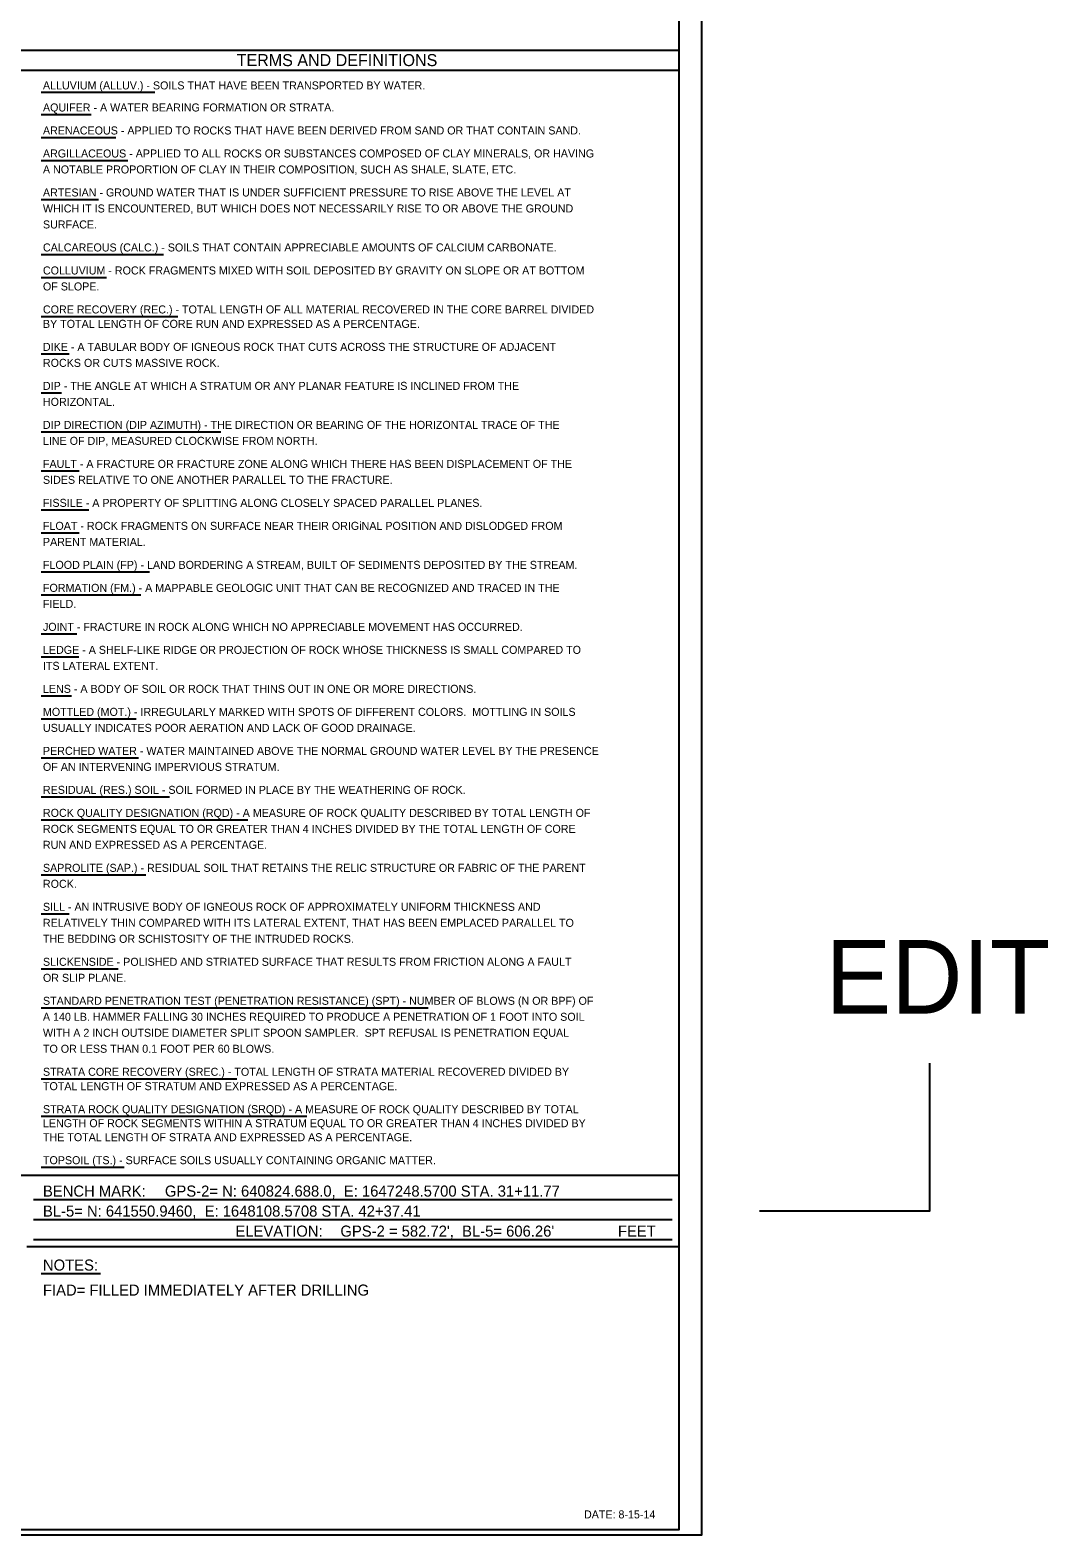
# Model space of a CAD drawing. Extents: x 278618 to 280654, y 171155 to 171855.
# Drawn here: x 280589 to 280644.2, y 171541.2 to 171622.8 of the extents above; entities that cross this region are included whole.
import ezdxf

# ---------------------------------------------------------------- set-up
doc = ezdxf.new("R2010")
doc.units = 0
for name, color, linetype in [('Geotech Sheets and Borders Cell', 7, 'Continuous'), ('Scratch_Level_4', 7, 'Continuous'), ('Sheet Plot Border Inside CELL', 7, 'Continuous')]:
    doc.layers.add(name, color=color, linetype=linetype)

msp = doc.modelspace()

# ---------------------------------------------------------------- linework, layer by layer
at = {"layer": 'Geotech Sheets and Borders Cell'}
for p, q in [((280474.148, 171621.702), (280624.148, 171621.702)), ((280474.148, 171620.618), (280624.148, 171620.618)), ((280589.583, 171619.412), (280595.75, 171619.412)), ((280589.583, 171618.216), (280592.292, 171618.216)), ((280589.583, 171616.969), (280593.621, 171616.969)), ((280589.583, 171615.722), (280594.282, 171615.722)), ((280589.583, 171613.608), (280592.696, 171613.608)), ((280589.583, 171610.627), (280596.206, 171610.627)), ((280589.583, 171609.38), (280593.123, 171609.38)), ((280589.583, 171607.266), (280596.989, 171607.266)), ((280589.583, 171605.237), (280591.097, 171605.237)), ((280589.583, 171603.123), (280590.683, 171603.123)), ((280589.583, 171601.009), (280599.327, 171601.009)), ((280589.583, 171598.895), (280591.633, 171598.895)), ((280589.583, 171596.781), (280592.157, 171596.781)), ((280589.583, 171595.534), (280591.633, 171595.534)), ((280589.583, 171593.42), (280595.448, 171593.42)), ((280589.583, 171592.173), (280594.985, 171592.173)), ((280589.583, 171590.059), (280591.511, 171590.059)), ((280589.583, 171588.811), (280591.63, 171588.811)), ((280589.583, 171586.697), (280591.232, 171586.697)), ((280589.583, 171585.45), (280594.735, 171585.45)), ((280589.583, 171583.336), (280594.86, 171583.336)), ((280589.583, 171581.222), (280596.536, 171581.222)), ((280589.583, 171579.975), (280600.791, 171579.975)), ((280589.583, 171576.994), (280595.255, 171576.994)), ((280589.583, 171574.88), (280591.097, 171574.88)), ((280589.583, 171571.899), (280593.749, 171571.899)), ((280589.583, 171569.785), (280610.558, 171569.785)), ((280589.583, 171565.937), (280600.187, 171565.937)), ((280589.583, 171563.909), (280603.989, 171563.909)), ((280624.148, 171560.688), (280549.148, 171560.688)), ((280589.583, 171561.144), (280594.08, 171561.144)), ((280589.158, 171559.386), (280623.792, 171559.386)), ((280589.158, 171558.301), (280623.792, 171558.301)), ((280589.158, 171557.216), (280623.792, 171557.216)), ((280588.802, 171556.835), (280624.148, 171556.835)), ((280589.583, 171555.376), (280592.804, 171555.376))]:
    msp.add_line(p, q, dxfattribs=at)
msp.add_lwpolyline([(280474.148, 171646.488), (280624.148, 171646.488), (280624.148, 171541.488), (280474.148, 171541.488)], close=True, dxfattribs=at)
at = {"layer": 'Scratch_Level_4'}
msp.add_lwpolyline([(280637.739, 171566.787), (280637.739, 171558.759), (280628.526, 171558.759)], dxfattribs=at)
at = {"layer": 'Sheet Plot Border Inside CELL'}
msp.add_lwpolyline([(280458.631, 171541.204), (280625.398, 171541.204), (280625.398, 171646.771), (280458.631, 171646.771)], close=True, dxfattribs=at)

# ---------------------------------------------------------------- texts
at = {"layer": 'Geotech Sheets and Borders Cell'}
for s, height, p in [('TERMS AND DEFINITIONS', 0.6507, (280600.181, 171620.834)), ('ALLUVIUM (ALLUV.) - SOILS THAT HAVE BEEN TRANSPORTED BY WATER.', 0.43381, (280589.677, 171619.57)), ('AQUIFER - A WATER BEARING FORMATION OR STRATA.', 0.43381, (280589.677, 171618.374)), ('ARENACEOUS - APPLIED TO ROCKS THAT HAVE BEEN DERIVED FROM SAND OR THAT CONTAIN SAND.', 0.43381, (280589.677, 171617.127)), ('ARGILLACEOUS - APPLIED TO ALL ROCKS OR SUBSTANCES COMPOSED OF CLAY MINERALS, OR HAVING', 0.43381, (280589.677, 171615.88)), ('A NOTABLE PROPORTION OF CLAY IN THEIR COMPOSITION, SUCH AS SHALE, SLATE, ETC.', 0.43381, (280589.677, 171615.013)), ('ARTESIAN - GROUND WATER THAT IS UNDER SUFFICIENT PRESSURE TO RISE ABOVE THE LEVEL AT', 0.43381, (280589.677, 171613.766)), ('WHICH IT IS ENCOUNTERED, BUT WHICH DOES NOT NECESSARILY RISE TO OR ABOVE THE GROUND', 0.43381, (280589.677, 171612.899)), ('SURFACE.', 0.4338, (280589.677, 171612.032)), ('CALCAREOUS (CALC.) - SOILS THAT CONTAIN APPRECIABLE AMOUNTS OF CALCIUM CARBONATE.', 0.43381, (280589.677, 171610.785)), ('COLLUVIUM - ROCK FRAGMENTS MIXED WITH SOIL DEPOSITED BY GRAVITY ON SLOPE OR AT BOTTOM ', 0.43381, (280589.677, 171609.538)), ('OF SLOPE.', 0.4338, (280589.677, 171608.671)), ('CORE RECOVERY (REC.) - TOTAL LENGTH OF ALL MATERIAL RECOVERED IN THE CORE BARREL DIVIDED', 0.43381, (280589.677, 171607.424)), ('BY TOTAL LENGTH OF CORE RUN AND EXPRESSED AS A PERCENTAGE.', 0.43381, (280589.677, 171606.643)), ('DIKE - A TABULAR BODY OF IGNEOUS ROCK THAT CUTS ACROSS THE STRUCTURE OF ADJACENT', 0.43381, (280589.677, 171605.396)), ('ROCKS OR CUTS MASSIVE ROCK.', 0.43381, (280589.677, 171604.529)), ('DIP - THE ANGLE AT WHICH A STRATUM OR ANY PLANAR FEATURE IS INCLINED FROM THE', 0.43381, (280589.677, 171603.282)), ('HORIZONTAL.', 0.43381, (280589.677, 171602.415)), ('DIP DIRECTION (DIP AZIMUTH) - THE DIRECTION OR BEARING OF THE HORIZONTAL TRACE OF THE', 0.43381, (280589.677, 171601.167)), ('LINE OF DIP, MEASURED CLOCKWISE FROM NORTH.', 0.43381, (280589.677, 171600.301)), ('FAULT - A FRACTURE OR FRACTURE ZONE ALONG WHICH THERE HAS BEEN DISPLACEMENT OF THE', 0.43381, (280589.677, 171599.053)), ('SIDES RELATIVE TO ONE ANOTHER PARALLEL TO THE FRACTURE.', 0.43381, (280589.677, 171598.187)), ('FISSILE - A PROPERTY OF SPLITTING ALONG CLOSELY SPACED PARALLEL PLANES.', 0.43381, (280589.677, 171596.939)), ('FLOAT - ROCK FRAGMENTS ON SURFACE NEAR THEIR ORIGiNAL POSITION AND DISLODGED FROM', 0.43381, (280589.677, 171595.692)), ('PARENT MATERIAL.', 0.43381, (280589.677, 171594.825)), ('FLOOD PLAIN (FP) - LAND BORDERING A STREAM, BUILT OF SEDIMENTS DEPOSITED BY THE STREAM.', 0.43381, (280589.677, 171593.578)), ('FORMATION (FM.) - A MAPPABLE GEOLOGIC UNIT THAT CAN BE RECOGNIZED AND TRACED IN THE', 0.43381, (280589.677, 171592.331)), ('FIELD.', 0.4338, (280589.677, 171591.464)), ('JOINT - FRACTURE IN ROCK ALONG WHICH NO APPRECIABLE MOVEMENT HAS OCCURRED.', 0.43381, (280589.677, 171590.217)), ('LEDGE - A SHELF-LIKE RIDGE OR PROJECTION OF ROCK WHOSE THICKNESS IS SMALL COMPARED TO', 0.43381, (280589.677, 171588.97)), ('ITS LATERAL EXTENT.', 0.43381, (280589.677, 171588.103)), ('LENS - A BODY OF SOIL OR ROCK THAT THINS OUT IN ONE OR MORE DIRECTIONS.', 0.43381, (280589.677, 171586.856)), ('MOTTLED (MOT.) - IRREGULARLY MARKED WITH SPOTS OF DIFFERENT COLORS.  MOTTLING IN SOILS', 0.43381, (280589.677, 171585.608)), ('USUALLY INDICATES POOR AERATION AND LACK OF GOOD DRAINAGE.', 0.43381, (280589.677, 171584.741)), ('PERCHED WATER - WATER MAINTAINED ABOVE THE NORMAL GROUND WATER LEVEL BY THE PRESENCE', 0.43381, (280589.677, 171583.494)), ('OF AN INTERVENING IMPERVIOUS STRATUM.', 0.43381, (280589.677, 171582.627)), ('RESIDUAL (RES.) SOIL - SOIL FORMED IN PLACE BY THE WEATHERING OF ROCK.', 0.43381, (280589.677, 171581.38)), ('ROCK QUALITY DESIGNATION (RQD) - A MEASURE OF ROCK QUALITY DESCRIBED BY TOTAL LENGTH OF ', 0.43381, (280589.677, 171580.133)), ('ROCK SEGMENTS EQUAL TO OR GREATER THAN 4 INCHES DIVIDED BY THE TOTAL LENGTH OF CORE', 0.43381, (280589.677, 171579.266)), ('RUN AND EXPRESSED AS A PERCENTAGE.', 0.43381, (280589.677, 171578.399)), ('SAPROLITE (SAP.) - RESIDUAL SOIL THAT RETAINS THE RELIC STRUCTURE OR FABRIC OF THE PARENT', 0.43381, (280589.677, 171577.152)), ('ROCK.', 0.4338, (280589.677, 171576.285)), ('SILL - AN INTRUSIVE BODY OF IGNEOUS ROCK OF APPROXIMATELY UNIFORM THICKNESS AND', 0.43381, (280589.677, 171575.038)), ('RELATIVELY THIN COMPARED WITH ITS LATERAL EXTENT, THAT HAS BEEN EMPLACED PARALLEL TO', 0.43381, (280589.677, 171574.171)), ('THE BEDDING OR SCHISTOSITY OF THE INTRUDED ROCKS.', 0.43381, (280589.677, 171573.304)), ('SLICKENSIDE - POLISHED AND STRIATED SURFACE THAT RESULTS FROM FRICTION ALONG A FAULT', 0.43381, (280589.677, 171572.057)), ('OR SLIP PLANE.', 0.43381, (280589.677, 171571.19)), ('STANDARD PENETRATION TEST (PENETRATION RESISTANCE) (SPT) - NUMBER OF BLOWS (N OR BPF) OF ', 0.43381, (280589.677, 171569.943)), ('A 140 LB. HAMMER FALLING 30 INCHES REQUIRED TO PRODUCE A PENETRATION OF 1 FOOT INTO SOIL', 0.43381, (280589.677, 171569.076)), ('WITH A 2 INCH OUTSIDE DIAMETER SPLIT SPOON SAMPLER.  SPT REFUSAL IS PENETRATION EQUAL', 0.43381, (280589.677, 171568.209)), ('TO OR LESS THAN 0.1 FOOT PER 60 BLOWS.', 0.43381, (280589.677, 171567.343)), ('STRATA CORE RECOVERY (SREC.) - TOTAL LENGTH OF STRATA MATERIAL RECOVERED DIVIDED BY', 0.43381, (280589.677, 171566.095)), ('TOTAL LENGTH OF STRATUM AND EXPRESSED AS A PERCENTAGE.', 0.43381, (280589.677, 171565.315)), ('STRATA ROCK QUALITY DESIGNATION (SRQD) - A MEASURE OF ROCK QUALITY DESCRIBED BY TOTAL', 0.43381, (280589.677, 171564.067)), ('LENGTH OF ROCK SEGMENTS WITHIN A STRATUM EQUAL TO OR GREATER THAN 4 INCHES DIVIDED BY', 0.43381, (280589.677, 171563.308)), ('THE TOTAL LENGTH OF STRATA AND EXPRESSED AS A PERCENTAGE.', 0.43381, (280589.677, 171562.549)), ('TOPSOIL (TS.) - SURFACE SOILS USUALLY CONTAINING ORGANIC MATTER.', 0.43381, (280589.677, 171561.302)), ('BENCH MARK:', 0.6, (280589.677, 171559.544)), ('GPS-2= N: 640824.688.0,  E: 1647248.5700 STA. 31+11.77', 0.6, (280596.291, 171559.544)), ('BL-5= N: 641550.9460,  E: 1648108.5708 STA. 42+37.41', 0.6, (280589.677, 171558.459)), ('ELEVATION:', 0.6, (280600.115, 171557.374)), ("GPS-2 = 582.72',  BL-5= 606.26'", 0.6, (280605.804, 171557.374)), ('FEET', 0.6, (280620.851, 171557.374)), ('NOTES:', 0.6, (280589.677, 171555.534)), ('FIAD= FILLED IMMEDIATELY AFTER DRILLING', 0.6, (280589.677, 171554.176)), ('DATE: 8-15-14', 0.43381, (280619.011, 171542.099))]:
    msp.add_text(s, height=height, dxfattribs=at).set_placement(p)
at = {"layer": 'Scratch_Level_4'}
msp.add_text('EDIT', height=4, dxfattribs=at).set_placement((280632.101, 171569.465))

doc.saveas('drawing.dxf')
